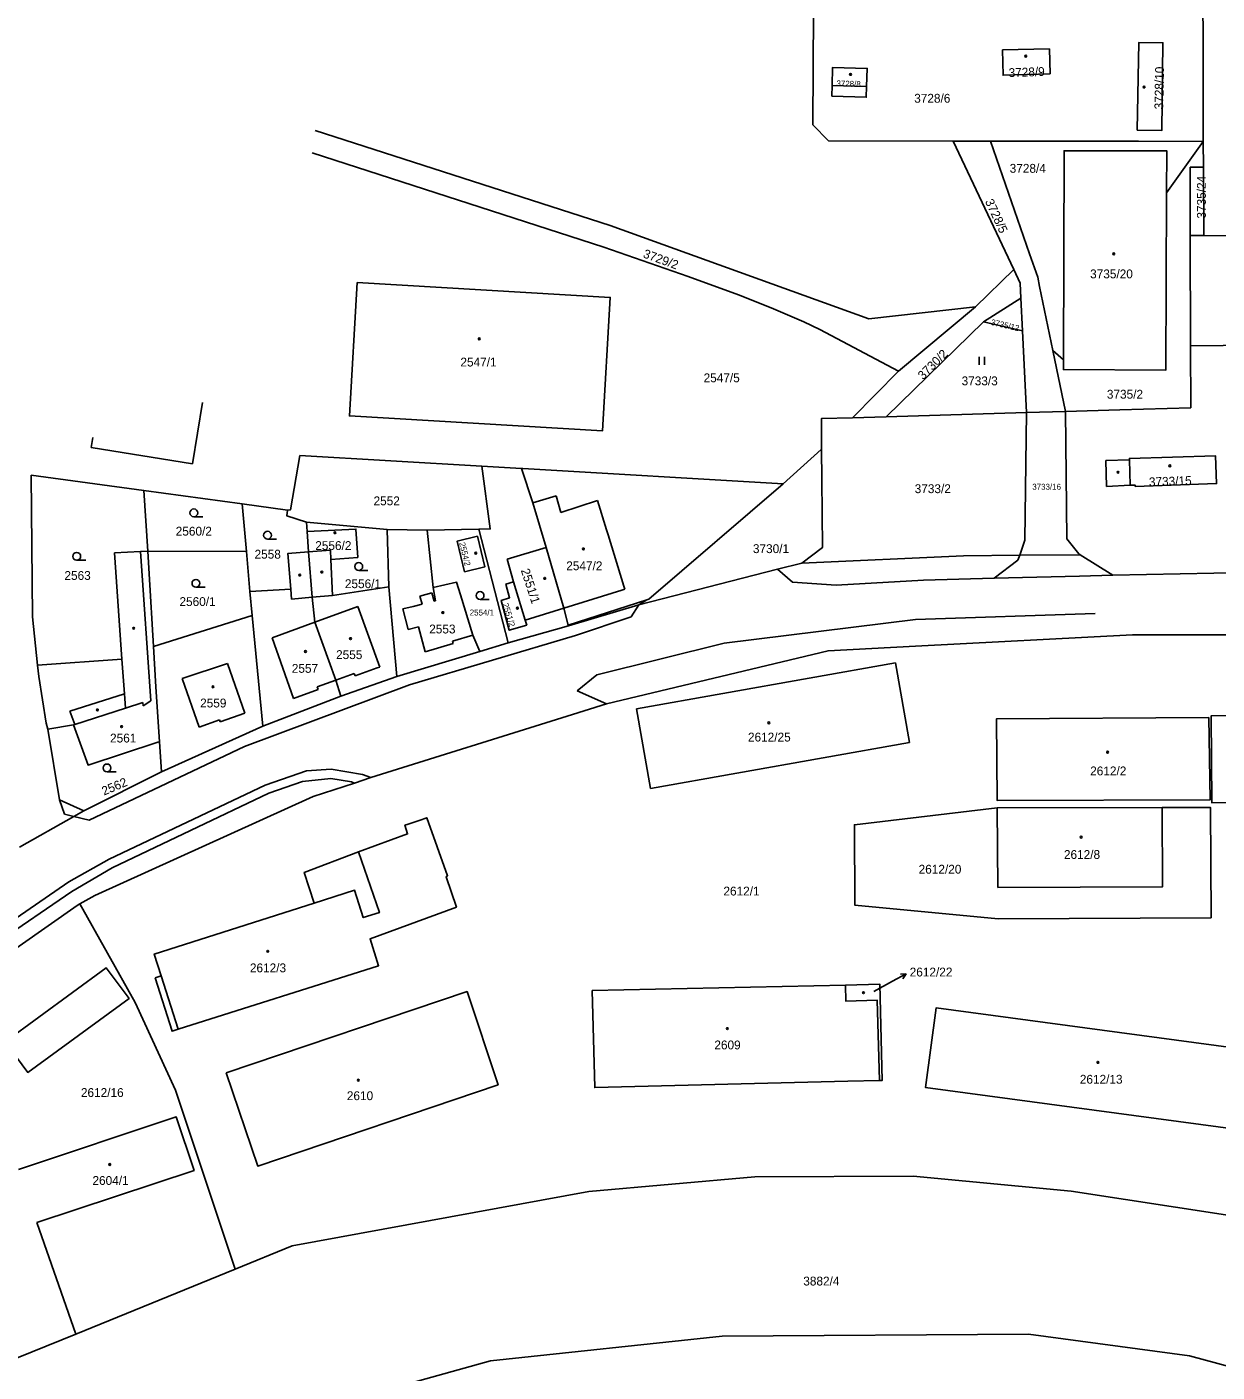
# Model space of a CAD drawing. Extents: x -527335 to -526256, y -1079142 to -1077836.
# Drawn here: x -526604.5 to -526375.8, y -1078442 to -1078183.4 of the extents above; entities that cross this region are included whole.
import ezdxf

# ---------------------------------------------------------------- set-up
doc = ezdxf.new("R2010")
doc.units = 0
for name, color, linetype in [('Hranice parcel', 7, 'Continuous'), ('Parcelní čísla', 7, 'Continuous'), ('Pop  PČ popisy', 7, 'Continuous'), ('Vnitřní kresba', 7, 'Continuous'), ('Značky budov', 7, 'Continuous'), ('Značky kultur', 7, 'Continuous')]:
    doc.layers.add(name, color=color, linetype=linetype)

msp = doc.modelspace()

# ---------------------------------------------------------------- linework, layer by layer
at = {"layer": 'Hranice parcel'}
for p, q in [((-526419.32, -1078205.33), (-526426.47, -1078205.32)), ((-526426.47, -1078205.32), (-526414.83, -1078230.01)), ((-526385.48, -1078215.29), (-526378.41, -1078205.42)), ((-526378.41, -1078205.42), (-526378.41, -1078205.39)), ((-526378.39, -1078210.36), (-526378.41, -1078205.42)), ((-526378.39, -1078210.36), (-526378.34, -1078223.51)), ((-526380.88, -1078244.69), (-526380.95, -1078223.47)), ((-526378.34, -1078223.51), (-526380.95, -1078223.47)), ((-526361.75, -1078223.62), (-526378.34, -1078223.51)), ((-526422.19, -1078237.19), (-526414.83, -1078230.01)), ((-526422.19, -1078237.19), (-526437.01, -1078249.59)), ((-526420.64, -1078240.08), (-526413.46, -1078235.55)), ((-526413.46, -1078235.55), (-526413.15, -1078241.83)), ((-526439.36, -1078258.33), (-526420.64, -1078240.08)), ((-526413.15, -1078241.83), (-526420.64, -1078240.08)), ((-526413.15, -1078241.83), (-526412.39, -1078257.53)), ((-526380.84, -1078256.6), (-526380.88, -1078244.69)), ((-526407.31, -1078245.62), (-526405.29, -1078247.41)), ((-526404.89, -1078257.31), (-526407.31, -1078245.62)), ((-526437.01, -1078249.59), (-526445.81, -1078258.52)), ((-526445.81, -1078258.52), (-526439.36, -1078258.33)), ((-526412.39, -1078257.53), (-526439.36, -1078258.33)), ((-526412.39, -1078257.53), (-526404.89, -1078257.31)), ((-526517.1, -1078267.83), (-526552.09, -1078265.78)), ((-526509.44, -1078268.28), (-526517.1, -1078267.83)), ((-526603.68, -1078269.57), (-526582.06, -1078272.51)), ((-526582.06, -1078272.51), (-526563.12, -1078275.09)), ((-526581.28, -1078284.16), (-526582.06, -1078272.51)), ((-526563.12, -1078275.09), (-526554.41, -1078276.28)), ((-526563.12, -1078275.09), (-526562.34, -1078284.26)), ((-526550.79, -1078278.6), (-526535.31, -1078279.99)), ((-526550.66, -1078280.39), (-526550.79, -1078278.6)), ((-526550.37, -1078284.3), (-526550.66, -1078280.39)), ((-526535.31, -1078279.99), (-526527.61, -1078280.13)), ((-526535.31, -1078279.99), (-526534.94, -1078291.05)), ((-526527.61, -1078280.13), (-526517.66, -1078279.92)), ((-526512.01, -1078301.8), (-526517.66, -1078279.92)), ((-526562.34, -1078284.26), (-526581.28, -1078284.16)), ((-526562.34, -1078284.26), (-526561.68, -1078291.96)), ((-526402.05, -1078284.87), (-526413.7, -1078284.97)), ((-526561.68, -1078291.96), (-526561.24, -1078296.54)), ((-526534.94, -1078291.05), (-526533.44, -1078308.28)), ((-526500.43, -1078298.57), (-526486.91, -1078294.51)), ((-526561.24, -1078296.54), (-526580.2, -1078302.53)), ((-526561.24, -1078296.54), (-526559.17, -1078317.84)), ((-526500.43, -1078298.57), (-526512.01, -1078301.8)), ((-526517.46, -1078303.45), (-526512.01, -1078301.8)), ((-526533.44, -1078308.28), (-526517.46, -1078303.45)), ((-526544.21, -1078312.08), (-526533.44, -1078308.28)), ((-526559.17, -1078317.84), (-526544.21, -1078312.08)), ((-526578.63, -1078326.6), (-526559.17, -1078317.84)), ((-526579.03, -1078320.85), (-526578.63, -1078326.6)), ((-526593.56, -1078334.08), (-526578.63, -1078326.6)), ((-526418.01, -1078333.56), (-526386.3, -1078333.5)), ((-526595.11, -1078434.71), (-526602.61, -1078413.24)), ((-526564.52, -1078422.23), (-526595.11, -1078434.71))]:
    msp.add_line(p, q, dxfattribs=at)
for points in [[(-526423.04, -1078162.78), (-526453.19, -1078162.9), (-526453.32, -1078180.38), (-526453.46, -1078202.22), (-526450.43, -1078205.28), (-526426.47, -1078205.32)], [(-526378.41, -1078205.39), (-526378.43, -1078198.99), (-526378.47, -1078188.81), (-526378.56, -1078162.53)], [(-526408, -1078187.59), (-526407.85, -1078192.39), (-526416.89, -1078192.68), (-526417, -1078187.81), (-526408, -1078187.59)], [(-526391.1, -1078203.25), (-526390.78, -1078186.36), (-526386.19, -1078186.43), (-526386.41, -1078203.31), (-526391.1, -1078203.25)], [(-526443.12, -1078194.85), (-526443.19, -1078196.9), (-526449.78, -1078196.68), (-526449.74, -1078194.62), (-526449.66, -1078191.15), (-526443, -1078191.35), (-526443.12, -1078194.85)], [(-526549.12, -1078203.3), (-526492.41, -1078221.56), (-526442.69, -1078239.51), (-526422.19, -1078237.19)], [(-526419.32, -1078205.33), (-526411.79, -1078227.04), (-526410.24, -1078231.51), (-526409.87, -1078233.29), (-526407.31, -1078245.62)], [(-526378.41, -1078205.39), (-526390.88, -1078205.37), (-526419.32, -1078205.33)], [(-526437.01, -1078249.59), (-526452.14, -1078241.56), (-526455.19, -1078240.06), (-526461.5, -1078237.38), (-526467.76, -1078234.87), (-526477.43, -1078231.38), (-526493.63, -1078225.7), (-526549.69, -1078207.6)], [(-526405.29, -1078247.41), (-526405.16, -1078207.2), (-526385.44, -1078207.2), (-526385.48, -1078215.29)], [(-526380.95, -1078223.47), (-526380.92, -1078210.35), (-526378.39, -1078210.36)], [(-526385.48, -1078215.29), (-526385.62, -1078249.41), (-526405.29, -1078249.27), (-526405.29, -1078247.41)], [(-526380.88, -1078244.69), (-526362.1, -1078244.53), (-526361.75, -1078223.62)], [(-526414.83, -1078230.01), (-526413.6, -1078232.64), (-526413.46, -1078235.55)], [(-526541.02, -1078232.54), (-526542.55, -1078258.17), (-526493.91, -1078261.05), (-526492.4, -1078235.4), (-526541.02, -1078232.54)], [(-526445.81, -1078258.52), (-526451.82, -1078258.7), (-526451.77, -1078264.59)], [(-526413.7, -1078284.97), (-526412.71, -1078282.05), (-526412.39, -1078257.53)], [(-526404.89, -1078257.31), (-526394.44, -1078257), (-526380.84, -1078256.6)], [(-526402.05, -1078284.87), (-526402.34, -1078284.69), (-526404.66, -1078281.84), (-526404.89, -1078257.31)], [(-526554.41, -1078276.28), (-526553.89, -1078276.24), (-526552.09, -1078265.78)], [(-526451.77, -1078264.59), (-526451.83, -1078264.65), (-526459.14, -1078271.25)], [(-526455.55, -1078286.46), (-526451.61, -1078283.5), (-526451.72, -1078270.38), (-526451.77, -1078264.59)], [(-526391.52, -1078271.72), (-526375.85, -1078271.18), (-526376.08, -1078265.82), (-526392.63, -1078266.34), (-526392.63, -1078266.63), (-526397.12, -1078266.78), (-526397.01, -1078271.73), (-526392.45, -1078271.49), (-526391.51, -1078271.5), (-526391.52, -1078271.72)], [(-526517.66, -1078279.92), (-526515.48, -1078279.9), (-526517.1, -1078267.83)], [(-526459.14, -1078271.25), (-526509.23, -1078268.29), (-526509.44, -1078268.28)], [(-526509.44, -1078268.28), (-526507.27, -1078274.88), (-526504.7, -1078283.5), (-526501.33, -1078295.15), (-526500.48, -1078298.39), (-526500.43, -1078298.57)], [(-526603.68, -1078269.57), (-526603.42, -1078296.84), (-526602.46, -1078306.07)], [(-526486.91, -1078294.51), (-526485.39, -1078293.57), (-526484.97, -1078293.44), (-526459.14, -1078271.25)], [(-526554.41, -1078276.28), (-526554.58, -1078277.36), (-526550.79, -1078278.6)], [(-526550.66, -1078280.39), (-526541.27, -1078279.93), (-526540.92, -1078285.37), (-526546.1, -1078285.76)], [(-526517.46, -1078303.45), (-526518.83, -1078300.36), (-526521.2, -1078292.56), (-526521.93, -1078290.16), (-526526.45, -1078291.14), (-526527.61, -1078280.13)], [(-526517.94, -1078281.3), (-526516.5, -1078287.17), (-526520.41, -1078288.14), (-526521.85, -1078282.27), (-526517.94, -1078281.3)], [(-526581.28, -1078284.16), (-526582.66, -1078284.24), (-526587.68, -1078284.52), (-526586.25, -1078304.95), (-526602.46, -1078306.07)], [(-526580.2, -1078302.53), (-526581, -1078288.51), (-526581.28, -1078284.16)], [(-526550.37, -1078284.3), (-526554.36, -1078284.61), (-526553.81, -1078291.49), (-526561.68, -1078291.96)], [(-526546.1, -1078285.76), (-526546.18, -1078283.97), (-526550.37, -1078284.3)], [(-526550.37, -1078284.3), (-526549.68, -1078293.05), (-526549.19, -1078297.86), (-526545.14, -1078308.97), (-526544.21, -1078312.08)], [(-526534.94, -1078291.05), (-526545.78, -1078292.7), (-526546.1, -1078285.76)], [(-526486.91, -1078294.51), (-526460.25, -1078287.66), (-526455.55, -1078286.46)], [(-526455.55, -1078286.46), (-526424.52, -1078285.05), (-526413.7, -1078284.97)], [(-526508.46, -1078298.42), (-526511.8, -1078299.38), (-526513.38, -1078293.64), (-526511.74, -1078293.15), (-526512.46, -1078290.51), (-526510.97, -1078290.06), (-526508.78, -1078297.46), (-526508.46, -1078298.42)], [(-526368.35, -1078300.3), (-526392.03, -1078300.3), (-526433.75, -1078302.47), (-526450.54, -1078303.34), (-526493.09, -1078313.52), (-526500.68, -1078315.9), (-526538.39, -1078327.72)], [(-526580.2, -1078302.53), (-526579.76, -1078310.28), (-526579.03, -1078320.85)], [(-526602.46, -1078306.07), (-526602.23, -1078308.27), (-526600.84, -1078317.27), (-526600.48, -1078318.43)], [(-526487.35, -1078314.49), (-526437.6, -1078305.66), (-526434.89, -1078320.97), (-526484.64, -1078329.8), (-526487.35, -1078314.49)], [(-526600.48, -1078318.43), (-526595.55, -1078317.59), (-526592.76, -1078325.31), (-526579.37, -1078320.89), (-526579.03, -1078320.85)], [(-526377.36, -1078316.15), (-526377.12, -1078332.02), (-526418.02, -1078332.15), (-526418.15, -1078316.42), (-526377.36, -1078316.15)], [(-526369.38, -1078332.51), (-526376.77, -1078332.6), (-526376.93, -1078315.85), (-526368.84, -1078315.76)], [(-526600.48, -1078318.43), (-526598.25, -1078331.97), (-526593.56, -1078334.08)], [(-526538.39, -1078327.72), (-526540.03, -1078327.15), (-526546.04, -1078326.1), (-526550.79, -1078326.44), (-526558.7, -1078329.17), (-526588.71, -1078343.39), (-526596.49, -1078347.76), (-526612.22, -1078358.58), (-526630.45, -1078371.95), (-526674.07, -1078406.52), (-526700.09, -1078429.86), (-526748.62, -1078475.19)], [(-526538.39, -1078327.72), (-526541.57, -1078328.76), (-526549.48, -1078331.36), (-526591.44, -1078350.37), (-526594.34, -1078352)], [(-526386.3, -1078333.5), (-526377, -1078333.48), (-526376.93, -1078354.66), (-526417.83, -1078354.85), (-526445.41, -1078352.22), (-526445.48, -1078336.8), (-526418.01, -1078333.56)], [(-526418.01, -1078333.56), (-526417.88, -1078348.85), (-526386.25, -1078348.7), (-526386.3, -1078333.5)], [(-526605.97, -1078341.1), (-526595.52, -1078335.19), (-526593.56, -1078334.08)], [(-526579.89, -1078366.21), (-526578.7, -1078365.84), (-526580.03, -1078361.64), (-526549.28, -1078351.86), (-526551.23, -1078345.94), (-526540.79, -1078341.97), (-526531.35, -1078338.54), (-526531.88, -1078336.89), (-526531.22, -1078336.66), (-526529.12, -1078335.94), (-526527.67, -1078335.44), (-526523.68, -1078346.59), (-526523.97, -1078346.77), (-526521.96, -1078352.62), (-526538.57, -1078358.72), (-526536.93, -1078363.9), (-526575.44, -1078376.12), (-526576.63, -1078376.5), (-526579.89, -1078366.21)], [(-526634.47, -1078380.43), (-526629.02, -1078376.22), (-526594.89, -1078352.31), (-526594.34, -1078352)], [(-526594.34, -1078352), (-526583.71, -1078370.94), (-526575.96, -1078387.79), (-526564.52, -1078422.23)], [(-526608.68, -1078378.53), (-526604.36, -1078384.41), (-526584.89, -1078370.18), (-526589.28, -1078364.31), (-526608.68, -1078378.53)], [(-526566.24, -1078384.51), (-526560.14, -1078402.42), (-526513.95, -1078386.77), (-526519.92, -1078368.86), (-526566.24, -1078384.51)], [(-526447.18, -1078367.61), (-526495.86, -1078368.67), (-526495.37, -1078387.34), (-526446.73, -1078386.12), (-526440.68, -1078385.97)], [(-526447.18, -1078367.61), (-526440.57, -1078367.47), (-526440.12, -1078385.94), (-526440.68, -1078385.97)], [(-526440.68, -1078385.97), (-526441.07, -1078370.54), (-526447.1, -1078370.73), (-526447.18, -1078367.61)], [(-526371.27, -1078395.48), (-526431.8, -1078387.34), (-526429.78, -1078372), (-526369.31, -1078380.15)], [(-526602.61, -1078413.24), (-526572.4, -1078403.26), (-526575.82, -1078392.96), (-526606.16, -1078403.06)], [(-526564.52, -1078422.23), (-526553.55, -1078417.76), (-526496.54, -1078407.33), (-526464.62, -1078404.48), (-526434.2, -1078404.33), (-526403.84, -1078407.24), (-526373.3, -1078411.92)], [(-526255.84, -1078485.88), (-526269.44, -1078477.46), (-526275.29, -1078479.08), (-526290.24, -1078467.75), (-526298.87, -1078468), (-526349.1, -1078447.58), (-526381.09, -1078438.93), (-526412.01, -1078434.75), (-526470.91, -1078435.12), (-526515.41, -1078439.88), (-526541.88, -1078447.21), (-526576.22, -1078459.13), (-526589.61, -1078459.9), (-526628.8, -1078481.46), (-526632.26, -1078483.8)], [(-526595.11, -1078434.71), (-526609.22, -1078440.47)]]:
    msp.add_lwpolyline(points, dxfattribs=at)
at = {"layer": 'Pop  PČ popisy'}
for p, q in [((-526441.75, -1078368.82), (-526438.16, -1078366.89)), ((-526438.16, -1078366.89), (-526435.51, -1078365.48)), ((-526435.51, -1078365.48), (-526436.63, -1078365.51)), ((-526435.51, -1078365.48), (-526436.16, -1078366.39))]:
    msp.add_line(p, q, dxfattribs=at)
at = {"layer": 'Vnitřní kresba'}
for p, q in [((-526449.74, -1078194.62), (-526443.12, -1078194.85)), ((-526570.79, -1078255.61), (-526572.71, -1078267.36)), ((-526592.15, -1078264.22), (-526591.85, -1078262.34)), ((-526572.71, -1078267.36), (-526592.15, -1078264.22)), ((-526392.45, -1078271.49), (-526392.63, -1078266.63)), ((-526507.27, -1078274.88), (-526502.8, -1078273.51)), ((-526502.8, -1078273.51), (-526501.88, -1078276.73)), ((-526501.88, -1078276.73), (-526494.86, -1078274.47)), ((-526494.86, -1078274.47), (-526493.13, -1078280.05)), ((-526493.13, -1078280.05), (-526492.83, -1078281.05)), ((-526492.83, -1078281.05), (-526489.77, -1078290.89)), ((-526580.68, -1078312.93), (-526582.66, -1078284.24)), ((-526504.7, -1078283.5), (-526512.24, -1078285.75)), ((-526510.97, -1078290.06), (-526512.24, -1078285.75)), ((-526418.6, -1078289.4), (-526414.03, -1078285.91)), ((-526414.03, -1078285.91), (-526413.7, -1078284.97)), ((-526395.78, -1078288.82), (-526402.05, -1078284.87)), ((-526460.25, -1078287.66), (-526457.34, -1078290.13)), ((-526432.22, -1078289.76), (-526418.6, -1078289.4)), ((-526418.6, -1078289.4), (-526402.24, -1078288.96)), ((-526395.78, -1078288.82), (-526402.24, -1078288.96)), ((-526362.42, -1078288.09), (-526395.78, -1078288.82)), ((-526553.81, -1078291.49), (-526553.66, -1078293.41)), ((-526526.45, -1078291.14), (-526525.97, -1078293.73)), ((-526501.33, -1078295.15), (-526490.17, -1078291.68)), ((-526489.58, -1078291.5), (-526490.17, -1078291.68)), ((-526489.58, -1078291.5), (-526489.77, -1078290.89)), ((-526457.34, -1078290.13), (-526448.99, -1078290.75)), ((-526448.99, -1078290.75), (-526432.22, -1078289.76)), ((-526553.66, -1078293.41), (-526549.68, -1078293.05)), ((-526549.68, -1078293.05), (-526545.78, -1078292.7)), ((-526530.3, -1078294.79), (-526528.56, -1078294.36)), ((-526528.97, -1078292.82), (-526526.69, -1078292.21)), ((-526528.56, -1078294.36), (-526528.97, -1078292.82)), ((-526526.69, -1078292.21), (-526526.27, -1078293.8)), ((-526526.27, -1078293.8), (-526525.97, -1078293.73)), ((-526500.48, -1078298.39), (-526485.39, -1078293.57)), ((-526488.41, -1078296.79), (-526486.91, -1078294.51)), ((-526549.19, -1078297.86), (-526540.93, -1078294.84)), ((-526540.93, -1078294.84), (-526536.71, -1078306.46)), ((-526532.28, -1078295.28), (-526530.3, -1078294.79)), ((-526531.23, -1078299.27), (-526532.28, -1078295.28)), ((-526508.78, -1078297.46), (-526501.33, -1078295.15)), ((-526499.07, -1078300.41), (-526488.41, -1078296.79)), ((-526470.52, -1078301.84), (-526433.76, -1078297.3)), ((-526433.76, -1078297.3), (-526399.18, -1078296.17)), ((-526549.19, -1078297.86), (-526557.36, -1078300.85)), ((-526529.28, -1078298.71), (-526531.23, -1078299.27)), ((-526529.28, -1078298.71), (-526527.95, -1078303.51)), ((-526557.36, -1078300.85), (-526553.26, -1078312.48)), ((-526531, -1078309.9), (-526499.07, -1078300.41)), ((-526527.95, -1078303.51), (-526522.58, -1078301.96)), ((-526522.72, -1078301.48), (-526518.83, -1078300.36)), ((-526522.58, -1078301.96), (-526522.72, -1078301.48)), ((-526495.01, -1078307.95), (-526470.52, -1078301.84)), ((-526585.78, -1078311.63), (-526586.25, -1078304.95)), ((-526574.69, -1078308.64), (-526565.98, -1078305.79)), ((-526565.98, -1078305.79), (-526562.63, -1078315.35)), ((-526537.22, -1078306.64), (-526541.44, -1078308.17)), ((-526536.71, -1078306.46), (-526537.22, -1078306.64)), ((-526571.44, -1078318), (-526574.69, -1078308.64)), ((-526562.73, -1078321.72), (-526531, -1078309.9)), ((-526548.73, -1078310.27), (-526545.14, -1078308.97)), ((-526541.61, -1078307.7), (-526545.14, -1078308.97)), ((-526541.44, -1078308.17), (-526541.61, -1078307.7)), ((-526498.73, -1078311.04), (-526495.01, -1078307.95)), ((-526596.26, -1078314.93), (-526585.78, -1078311.63)), ((-526585.78, -1078311.63), (-526585.59, -1078314.37)), ((-526553.26, -1078312.48), (-526548.55, -1078310.77)), ((-526548.55, -1078310.77), (-526548.73, -1078310.27)), ((-526493.09, -1078313.52), (-526498.73, -1078311.04)), ((-526595.32, -1078317.51), (-526596.26, -1078314.93)), ((-526585.59, -1078314.37), (-526595.32, -1078317.51)), ((-526585.59, -1078314.37), (-526582.26, -1078313.29)), ((-526582.26, -1078313.29), (-526582.2, -1078313.93)), ((-526582.2, -1078313.93), (-526580.68, -1078312.93)), ((-526562.63, -1078315.35), (-526567.37, -1078316.99)), ((-526595.55, -1078317.59), (-526595.32, -1078317.51)), ((-526567.5, -1078316.63), (-526571.44, -1078318)), ((-526567.37, -1078316.99), (-526567.5, -1078316.63)), ((-526592.55, -1078335.89), (-526562.73, -1078321.72)), ((-526551.52, -1078328.5), (-526546.11, -1078327.89)), ((-526546.11, -1078327.89), (-526542.14, -1078328.56)), ((-526558.03, -1078330.71), (-526588.12, -1078345.09)), ((-526558.03, -1078330.71), (-526551.52, -1078328.5)), ((-526542.14, -1078328.56), (-526541.57, -1078328.76)), ((-526598.25, -1078331.97), (-526597.3, -1078334.78)), ((-526597.3, -1078334.78), (-526595.52, -1078335.19)), ((-526595.52, -1078335.19), (-526592.55, -1078335.89)), ((-526588.12, -1078345.09), (-526595.86, -1078349.62)), ((-526595.86, -1078349.62), (-526611.05, -1078360)), ((-526575.44, -1078376.12), (-526578.7, -1078365.84))]:
    msp.add_line(p, q, dxfattribs=at)
msp.add_lwpolyline([(-526540.79, -1078341.97), (-526536.78, -1078353.66), (-526539.86, -1078354.65), (-526541.53, -1078349.39), (-526549.28, -1078351.86)], dxfattribs=at)
at = {"layer": 'Značky budov'}
for centre in [(-526412.54, -1078188.99), (-526446.21, -1078192.51), (-526389.8, -1078194.94), (-526395.63, -1078227), (-526517.58, -1078243.36), (-526394.81, -1078269.01), (-526384.84, -1078267.78), (-526545.31, -1078280.63), (-526497.56, -1078283.75), (-526518.26, -1078284.58), (-526552.08, -1078288.78), (-526547.84, -1078288.2), (-526505, -1078289.42), (-526524.57, -1078295.99), (-526510.25, -1078295.15), (-526584, -1078299.01), (-526542.32, -1078301), (-526550.98, -1078303.48), (-526568.75, -1078310.26), (-526590.97, -1078314.71), (-526586.32, -1078317.92), (-526461.92, -1078317.18), (-526396.81, -1078322.84), (-526401.89, -1078339.17), (-526558.24, -1078361.13), (-526443.73, -1078369.07), (-526469.9, -1078375.99), (-526398.66, -1078382.48), (-526540.82, -1078385.91), (-526588.6, -1078402.11)]:
    msp.add_circle(centre, 0.175, dxfattribs=at)
at = {"layer": 'Značky kultur'}
for p, q in [((-526421.48, -1078248.34), (-526421.48, -1078246.84)), ((-526420.48, -1078248.34), (-526420.48, -1078246.84)), ((-526572.44, -1078277.57), (-526570.69, -1078277.57)), ((-526558.27, -1078281.86), (-526556.52, -1078281.86)), ((-526594.94, -1078285.93), (-526593.19, -1078285.93)), ((-526540.74, -1078287.88), (-526538.99, -1078287.88)), ((-526572.04, -1078291.11), (-526570.29, -1078291.11)), ((-526517.42, -1078293.46), (-526515.67, -1078293.46)), ((-526589.12, -1078326.61), (-526587.37, -1078326.61))]:
    msp.add_line(p, q, dxfattribs=at)
for centre in [(-526572.44, -1078276.82), (-526558.27, -1078281.11), (-526594.94, -1078285.18), (-526540.74, -1078287.13), (-526572.04, -1078290.36), (-526517.42, -1078292.71), (-526589.12, -1078325.86)]:
    msp.add_circle(centre, 0.75, dxfattribs=at)

# ---------------------------------------------------------------- texts
at = {"layer": 'Parcelní čísla'}
for s, height, rotation, p in [('3728/9', 1.7, 2, (-526415.81, -1078193.03)), ('3728/10', 1.7, 89, (-526386.11, -1078199.25)), ('3728/8', 1.14, 358, (-526448.94, -1078194.79)), ('3735/24', 1.7, 90, (-526377.93, -1078220.23)), ('3728/5', 1.7, 295, (-526420.41, -1078216.93)), ('3729/2', 1.7, 340, (-526486.22, -1078227.66)), ('3735/12', 1.14, 347, (-526419.31, -1078240.66)), ('3730/2', 1.7, 45, (-526432.28, -1078251.33)), ('3733/15', 1.7, 2, (-526388.84, -1078271.72)), ('2554/2', 1.14, 284, (-526521.45, -1078282.62)), ('2551/1', 1.7, 288, (-526509.61, -1078287.84)), ('2551/2', 1.139, 287, (-526513.1, -1078294.37)), ('2562', 1.7, 23, (-526589.7, -1078331.19))]:
    msp.add_text(s, height=height, rotation=rotation, dxfattribs=at).set_placement(p)
for s, height, p in [('3728/6', 1.7, (-526433.98, -1078197.95)), ('3728/4', 1.7, (-526415.63, -1078211.42)), ('3735/20', 1.7, (-526400.17, -1078231.72)), ('2547/1', 1.7, (-526521.2, -1078248.67)), ('2547/5', 1.7, (-526474.46, -1078251.7)), ('3733/3', 1.7, (-526424.87, -1078252.29)), ('3735/2', 1.7, (-526396.95, -1078254.86)), ('3733/2', 1.7, (-526433.89, -1078273.02)), ('3733/16', 1.139, (-526411.28, -1078272.37)), ('2552', 1.7, (-526537.9, -1078275.36)), ('2560/2', 1.7, (-526575.92, -1078281.19)), ('2558', 1.7, (-526560.77, -1078285.62)), ('2556/2', 1.7, (-526549.1, -1078283.96)), ('3730/1', 1.7, (-526464.98, -1078284.55)), ('2547/2', 1.7, (-526500.86, -1078287.84)), ('2563', 1.7, (-526597.31, -1078289.71)), ('2556/1', 1.7, (-526543.41, -1078291.29)), ('2560/1', 1.7, (-526575.2, -1078294.73)), ('2554/1', 1.14, (-526519.41, -1078296.55)), ('2553', 1.7, (-526527.2, -1078300)), ('2555', 1.7, (-526545.1, -1078304.93)), ('2557', 1.7, (-526553.61, -1078307.57)), ('2559', 1.7, (-526571.23, -1078314.23)), ('2561', 1.7, (-526588.54, -1078320.97)), ('2612/25', 1.7, (-526465.93, -1078320.78)), ('2612/2', 1.7, (-526400.16, -1078327.29)), ('2612/8', 1.7, (-526405.2, -1078343.36)), ('2612/20', 1.7, (-526433.13, -1078346.19)), ('2612/1', 1.7, (-526470.65, -1078350.39)), ('2612/3', 1.7, (-526561.66, -1078365.16)), ('2612/22', 1.7, (-526434.85, -1078365.96)), ('2609', 1.7, (-526472.39, -1078379.98)), ('2612/13', 1.7, (-526402.15, -1078386.58)), ('2612/16', 1.7, (-526594.14, -1078389.13)), ('2610', 1.7, (-526543.03, -1078389.74)), ('2604/1', 1.7, (-526591.92, -1078406.04)), ('3882/4', 1.7, (-526455.3, -1078425.38))]:
    msp.add_text(s, height=height, dxfattribs=at).set_placement(p)

doc.saveas('drawing.dxf')
